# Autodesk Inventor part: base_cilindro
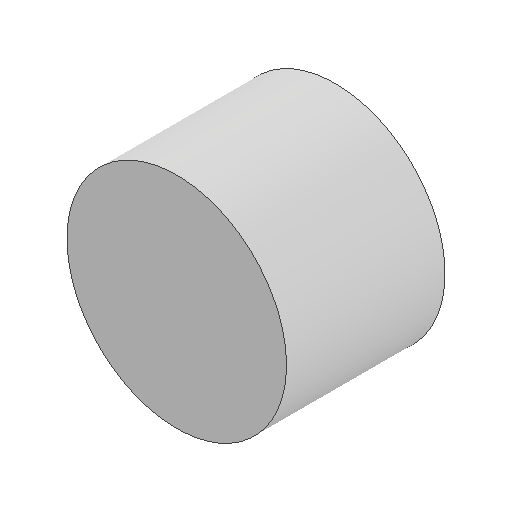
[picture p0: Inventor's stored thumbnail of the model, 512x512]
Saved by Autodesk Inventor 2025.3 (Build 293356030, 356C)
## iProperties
Created: 2026-03
Part Number: base_cilindro
Material: Generico
Document SubType Name: Modeling
Designer: Ryzen5700u
Density: 1 g/cm^3
Appearance: Default
Author: Ryzen5700u
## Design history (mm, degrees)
sketch "Schizzo1"
  geometry: L1 (-11.5, 6.25)-(-11.5, -6.25) reference; L2 (-11.5, 6.25)-(-16.1, 6.25) reference; L3 (-16.1, 6.25)-(-16.1, 0.6) reference; L4 (-16.1, 0.6)-(-14.7, 0.6) reference; L5 (-14.7, -0.6)-(-16.1, -0.6) reference; L6 (-16.1, -0.6)-(-16.1, -6.25) reference; L7 (-11.5, -6.25)-(-16.1, -6.25) reference; L8 (11.5, -6.25)-(11.5, 6.25) reference; L9 (11.5, -6.25)-(16.1, -6.25) reference; L10 (16.1, -6.25)-(16.1, -0.6) reference; L11 (16.1, -0.6)-(14.7, -0.6) reference; L12 (14.7, 0.6)-(16.1, 0.6) reference; L13 (16.1, 0.6)-(16.1, 6.25) reference; L14 (11.5, 6.25)-(16.1, 6.25) reference; L15 (11.5, -6.25)-(17.5, -6.25); L16 (17.5, -6.25)-(17.5, 6.25); L17 (17.5, 6.25)-(11.5, 6.25); L18 (11.5, 6.25)-(11.5, -6.25); L19 (-11.5, -6.25)-(-17.5, -6.25); L20 (-17.5, -6.25)-(-17.5, 6.25); L21 (-17.5, 6.25)-(-11.5, 6.25); L22 (-11.5, 6.25)-(-11.5, -6.25); C1 r 1 at (13.9, 0); C2 r 1 at (-13.9, 0); A1 r 1 centre (-13.9, 0) between (-14.7, -0.6) and (-14.7, 0.6) reference; A2 r 1 centre (13.9, 0) between (14.7, 0.6) and (14.7, -0.6) reference; 9 further points
  constraints: 16 end point, 4 parallel, 2 centre point, 2 coincident, 2 concentric, 2 horizontal, 2 perpendicular, 1 point on line
  dimensions: "d0" = 6 distance of L17.end L16.end; "d1" = 6 distance of L20.end L21.end
extrude "Estrusione1" new body sketch "Schizzo1" distance "d2" = 18.8; taper "d3" = 0 deg
sketch "Schizzo2"
  geometry: C1 r 27 at (5.65, 0); C2 r 25 at (5.65, 0); A1 r 27 centre (5.65, 0) between (25.775, -18) and (-14.475, -18) reference; A2 r 25 centre (5.65, 0) between (24.859, -16) and (-13.559, -16); 5 further points
  constraints: 3 centre point, 2 coincident, 2 point on circle, 1 concentric
extrude "Estrusione2" join sketch "Schizzo2" distance "d5" = 34; taper "d6" = 0 deg
sketch "Schizzo3"
  geometry: L1 (-14.475, -18)-(25.775, -18) reference; L2 (-17.5, 6.25)-(-17.5, -6.25) reference; L3 (-11.5, 6.25)-(-17.5, 6.25) reference; L4 (-11.5, -6.25)-(-11.5, 6.25) reference; L5 (-17.5, -6.25)-(-11.5, -6.25) reference; L6 (-17.5, 6.25)-(-18.556, 6.25); L7 (-17.5, -6.25)-(-18.556, -6.25); C1 r 27 at (5.65, 0) reference; A1 r 27 centre (5.65, 0) between (25.775, -18) and (-14.475, -18) reference; A2 r 25 centre (5.65, 0) between (-18.556, 6.25) and (-18.556, -6.25) reference; 1 further point
  constraints: 4 end point, 2 horizontal, 2 point on circle
  node "Linea chiusa proiettata1"
  node "Linea chiusa proiettata2"
extrude "Estrusione3" join sketch "Schizzo3" distance "d7" = 5; taper "d8" = 0 deg
extrude "Estrusione4" join sketch "Schizzo3" stored distance "d9" = 10; taper "d10" = 0 deg
sketch "Schizzo4"
  geometry: L1 (-12.9, 18.8)-(-12.9, 0) reference; L2 (-17.5, 0)-(-17.5, 18.8) reference; L3 (-12.9, 12.3)-(-17.5, 12.3); L4 (-17.5, 12.3)-(-17.5, 16.3); L5 (-17.5, 16.3)-(-12.9, 16.3); L6 (-12.9, 16.3)-(-12.9, 12.3); L7 (-14.9, 18.8)-(-12.9, 18.8) reference; L8 (-12.9, 12.3)-(-11.336, 12.3); L9 (-11.336, 12.3)-(-11.336, 16.3); L10 (-11.336, 16.3)-(-12.9, 16.3); L11 (-12.9, 16.3)-(-12.9, 12.3); 4 further points
  constraints: 16 end point, 4 parallel, 2 horizontal, 2 perpendicular, 2 point on line
  dimensions: "d11" = 4 distance between parallel lines of L5 L3; "d12" = 2.5 distance between parallel lines of L7 L5
extrude "Estrusione5" cut sketch "Schizzo4" stored distance "d13" = 7; taper "d14" = 0 deg
sketch "Schizzo5"
  geometry: L1 (6, -12.3)-(6, -16.3) reference; L2 (0, -16.3)-(0, -12.3) reference; L3 (6, -16.3)-(0, -16.3) reference; L4 (0, -12.3)-(6, -12.3) reference; 1 further point
extrude "Estrusione6" cut sketch "Schizzo5" distance "d15" = 5; taper "d16" = 0 deg
chamfer "Smusso1" distance "d17" = 2; stored, may be unused: second distance "d18" = 2, angle "d19" = 45 deg
sketch "Schizzo7"
  geometry: A1 r 1 centre (13.9, 0) between (14.7, 0.6) and (14.7, -0.6) reference; A2 r 1 centre (-13.9, 0) between (-14.7, -0.6) and (-14.7, 0.6) reference; 1 further point
hole "Foro1" sketch "Schizzo7" at (13.9, 0), (-13.9, 0) diameter "d22" = 1.8; stored, may be unused: countersink angle "d26" = 90 deg, drill point angle "d28" = 118 deg; dims "d23" = 6, "d24" = 3.5, "d25" = 1.8, "d27" = 8
node "Piano di lavoro1"
node "Solido1"
node "Riferimento1"
node "Riferimento2"
node "Linea chiusa proiettata3"
node "Riferimento4"
node "Riferimento5"
